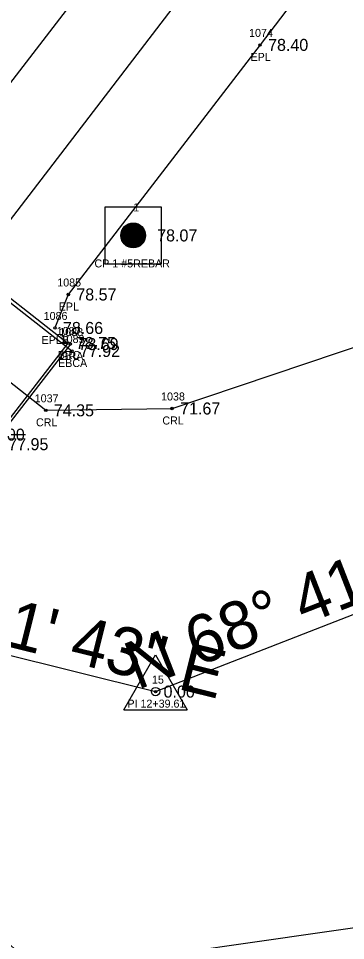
# Model space of a CAD drawing. Extents: x 2505249 to 2506333, y 912937 to 914171.
# Drawn here: x 2505829.2 to 2505870.1, y 913450.7 to 913565.9 of the extents above; entities that cross this region are included whole.
import ezdxf

# ---------------------------------------------------------------- set-up
doc = ezdxf.new("R2010")
doc.units = 0
for name, color, linetype in [('RD_EX_Bridge', 7, 'Continuous'), ('RD_EX_Bridge_txCode', 7, 'Continuous'), ('RD_EX_GuardRail', 7, 'Continuous'), ('RD_EX_GuardRail_txCode', 7, 'Continuous'), ('RD_EX_H2O', 7, 'Continuous'), ('RD_EX_H2O_txCode', 7, 'Continuous'), ('RD_EX_Misc', 7, 'Continuous'), ('RD_EX_Road', 7, 'Continuous'), ('RD_EX_Road_txCode', 7, 'Continuous'), ('RD_EX_TX_Bridge_ELEV', 7, 'Continuous'), ('RD_EX_TX_GuardRail_ELEV', 7, 'Continuous'), ('RD_EX_TX_H2O_ELEV', 7, 'Continuous'), ('RD_EX_TX_Misc_ELEV', 7, 'Continuous'), ('RD_EX_TX_Road_ELEV', 7, 'Continuous'), ('RD_HC_Cl', 7, 'Continuous'), ('RD_HC_Data', 7, 'Continuous'), ('RD_HC_Survey', 7, 'Continuous'), ('RD_HC_Survey_ELEV', 7, 'Continuous'), ('RD_HC_Survey_txCode', 7, 'Continuous'), ('RD_HC_txCode', 7, 'Continuous'), ('RD_SMD_Locator', 7, 'Continuous')]:
    doc.layers.add(name, color=color, linetype=linetype)

msp = doc.modelspace()

# ---------------------------------------------------------------- linework, layer by layer
at = {"layer": 'RD_EX_Bridge'}
msp.add_line((2505835.88, 913524.37), (2505809.62, 913544.86), dxfattribs=at)
msp.add_lwpolyline([(2505810.9, 913544.51), (2505835.38, 913525.37), (2505780.21, 913454.04), (2505755.58, 913473.5), (2505810.9, 913544.51)], dxfattribs=at)
at = {"layer": 'RD_EX_GuardRail'}
msp.add_line((2505835.7, 913525.24), (2505780.23, 913453.67), dxfattribs=at)
at = {"layer": 'RD_EX_H2O'}
for points in [[(2505762.26, 913658.11), (2505746.15, 913644.25), (2505726.47, 913615.21), (2505674.21, 913628.01), (2505666.25, 913620.58), (2505714.6, 913592.15), (2505793.9, 913560.45), (2505801.32, 913552.8), (2505803.7, 913539.77), (2505832.63, 913516.96), (2505848.42, 913517.19), (2505881.86, 913528.44), (2505910.2, 913538.78), (2505939.3, 913544.45), (2505946.25, 913542.54), (2505974.65, 913535.18), (2506004.11, 913524.7), (2506052.03, 913515.47), (2506115.49, 913494.68), (2506138.05, 913548.89)], [(2505789.47, 913464.31), (2505795.69, 913463.1), (2505812.13, 913464.37), (2505832.03, 913446.73), (2505876.17, 913453.08), (2505891.76, 913474.03), (2505941.74, 913475.13), (2505995.42, 913465.05), (2506040.13, 913447.4), (2506076.3, 913432.47), (2506096.96, 913385.48)]]:
    msp.add_lwpolyline(points, dxfattribs=at)
at = {"layer": 'RD_EX_Misc'}
msp.add_line((2505820.09, 913513.92), (2505830.09, 913513.92), dxfattribs=at)
at = {"layer": 'RD_EX_Road'}
for points in [[(2506024.03, 913813.1), (2505962.01, 913732.06), (2505903.3, 913655.93), (2505840.88, 913574.4), (2505819.41, 913546.54), (2505814.19, 913542.64)], [(2506040.71, 913800.23), (2505979.73, 913720.47), (2505920.44, 913642.61), (2505859.42, 913562.61), (2505835.44, 913531.43), (2505833.77, 913527.25)]]:
    msp.add_lwpolyline(points, dxfattribs=at)
at = {"layer": 'RD_HC_Cl'}
for p, q in [((2505792.76, 913494.51), (2506032.34, 913807.1)), ((2505846.35, 913481.82), (2505891.84, 913499.56)), ((2505811.03, 913490.61), (2505846.35, 913481.82))]:
    msp.add_line(p, q, dxfattribs=at)
at = {"layer": 'RD_HC_Data'}
for p, q in [((2505842.38, 913479.53), (2505846.35, 913486.41)), ((2505846.35, 913486.41), (2505850.32, 913479.53)), ((2505842.38, 913479.53), (2505850.32, 913479.53))]:
    msp.add_line(p, q, dxfattribs=at)
msp.add_circle((2505846.35, 913481.82), 0.529, dxfattribs=at)
at = {"layer": 'RD_HC_Survey'}
for p, q in [((2505842.24, 913537.97), (2505842.24, 913539.64)), ((2505842.29, 913537.9), (2505842.29, 913539.71)), ((2505842.34, 913537.83), (2505842.34, 913539.78)), ((2505842.39, 913537.77), (2505842.39, 913539.84)), ((2505842.44, 913537.72), (2505842.44, 913539.89)), ((2505842.49, 913537.67), (2505842.49, 913539.94)), ((2505842.54, 913537.63), (2505842.54, 913539.99)), ((2505842.59, 913537.58), (2505842.59, 913540.03)), ((2505842.64, 913537.55), (2505842.64, 913540.06)), ((2505842.69, 913537.51), (2505842.69, 913540.1)), ((2505842.74, 913537.48), (2505842.74, 913540.13)), ((2505842.79, 913537.45), (2505842.79, 913540.16)), ((2505842.84, 913537.42), (2505842.84, 913540.19)), ((2505842.89, 913537.4), (2505842.89, 913540.21)), ((2505842.94, 913537.38), (2505842.94, 913540.23)), ((2505842.99, 913537.36), (2505842.99, 913540.25)), ((2505843.04, 913537.34), (2505843.04, 913540.27)), ((2505843.09, 913537.32), (2505843.09, 913540.29)), ((2505843.14, 913537.31), (2505843.14, 913540.3)), ((2505843.19, 913537.29), (2505843.19, 913540.32)), ((2505843.24, 913537.28), (2505843.24, 913540.33)), ((2505843.29, 913537.27), (2505843.29, 913540.34)), ((2505843.34, 913537.27), (2505843.34, 913540.35)), ((2505843.39, 913537.26), (2505843.39, 913540.35)), ((2505843.44, 913537.25), (2505843.44, 913540.36)), ((2505843.49, 913537.25), (2505843.49, 913540.36)), ((2505843.54, 913537.25), (2505843.54, 913540.36)), ((2505843.59, 913537.25), (2505843.59, 913540.36)), ((2505843.64, 913537.25), (2505843.64, 913540.36)), ((2505843.69, 913537.26), (2505843.69, 913540.35)), ((2505843.74, 913537.26), (2505843.74, 913540.35)), ((2505843.79, 913537.27), (2505843.79, 913540.34)), ((2505843.84, 913537.28), (2505843.84, 913540.33)), ((2505843.89, 913537.29), (2505843.89, 913540.32)), ((2505843.94, 913537.3), (2505843.94, 913540.31)), ((2505843.99, 913537.31), (2505843.99, 913540.3)), ((2505844.04, 913537.33), (2505844.04, 913540.28)), ((2505844.09, 913537.35), (2505844.09, 913540.26)), ((2505844.14, 913537.37), (2505844.14, 913540.24)), ((2505844.19, 913537.39), (2505844.19, 913540.22)), ((2505844.24, 913537.41), (2505844.24, 913540.2)), ((2505844.29, 913537.44), (2505844.29, 913540.17)), ((2505844.34, 913537.47), (2505844.34, 913540.15)), ((2505844.39, 913537.5), (2505844.39, 913540.11)), ((2505844.44, 913537.53), (2505844.44, 913540.08)), ((2505844.49, 913537.57), (2505844.49, 913540.04)), ((2505844.54, 913537.61), (2505844.54, 913540.01)), ((2505844.59, 913537.65), (2505844.59, 913539.96)), ((2505844.64, 913537.69), (2505844.64, 913539.92)), ((2505844.69, 913537.75), (2505844.69, 913539.86)), ((2505844.74, 913537.8), (2505844.74, 913539.81)), ((2505844.79, 913537.87), (2505844.79, 913539.75)), ((2505844.84, 913537.93), (2505844.84, 913539.68)), ((2505842.04, 913538.44), (2505842.04, 913539.17)), ((2505842.09, 913538.28), (2505842.09, 913539.33)), ((2505842.14, 913538.15), (2505842.14, 913539.46)), ((2505842.19, 913538.06), (2505842.19, 913539.55)), ((2505844.89, 913538.01), (2505844.89, 913539.6)), ((2505844.94, 913538.11), (2505844.94, 913539.51)), ((2505844.99, 913538.21), (2505844.99, 913539.4)), ((2505845.04, 913538.36), (2505845.04, 913539.25)), ((2505845.09, 913538.58), (2505845.09, 913539.03))]:
    msp.add_line(p, q, dxfattribs=at)
msp.add_lwpolyline([(2505847.08, 913542.34), (2505840.01, 913542.34), (2505840.01, 913535.27), (2505847.08, 913535.27)], close=True, dxfattribs=at)
msp.add_circle((2505843.55, 913538.81), 1.55, dxfattribs=at)
at = {"layer": 'RD_SMD_Locator'}
for centre in [(2505859.42, 913562.61), (2505843.55, 913538.81), (2505835.44, 913531.43), (2505833.77, 913527.25), (2505835.38, 913525.37), (2505835.7, 913525.24), (2505835.88, 913524.37), (2505832.63, 913516.96), (2505848.42, 913517.19), (2505846.35, 913481.82)]:
    msp.add_circle(centre, 0.15, dxfattribs=at)

# ---------------------------------------------------------------- texts
at = {"layer": 'RD_EX_Bridge_txCode'}
for s, p in [('1087', (2505833.99, 913526.37)), ('1089', (2505834.49, 913525.37)), ('BRC', (2505834.12, 913523.37)), ('EBCA', (2505834.16, 913522.37))]:
    msp.add_text(s, height=1, dxfattribs=at).set_placement(p)
at = {"layer": 'RD_EX_GuardRail_txCode'}
for s, p in [('1088', (2505834.31, 913526.24)), ('GRA', (2505834.43, 913523.24))]:
    msp.add_text(s, height=1, dxfattribs=at).set_placement(p)
at = {"layer": 'RD_EX_H2O_txCode'}
for s, p in [('1037', (2505831.24, 913517.96)), ('1038', (2505847.04, 913518.19)), ('CRL', (2505831.4, 913514.96)), ('CRL', (2505847.2, 913515.19))]:
    msp.add_text(s, height=1, dxfattribs=at).set_placement(p)
at = {"layer": 'RD_EX_Road_txCode'}
for s, p in [('1074', (2505858.04, 913563.61)), ('EPL', (2505858.22, 913560.61)), ('1085', (2505834.06, 913532.43)), ('EPL', (2505834.24, 913529.43)), ('1086', (2505832.36, 913528.25)), ('EPLB', (2505832.09, 913525.25))]:
    msp.add_text(s, height=1, dxfattribs=at).set_placement(p)
at = {"layer": 'RD_EX_TX_Bridge_ELEV'}
for s, p in [('78.75', (2505836.38, 913524.62)), ('77.92', (2505836.88, 913523.62)), ('77.95', (2505827.93, 913511.98))]:
    msp.add_text(s, height=1.5, dxfattribs=at).set_placement(p)
at = {"layer": 'RD_EX_TX_GuardRail_ELEV'}
msp.add_text('78.69', height=1.5, dxfattribs=at).set_placement((2505836.7, 913524.49))
at = {"layer": 'RD_EX_TX_H2O_ELEV'}
for s, p in [('71.67', (2505849.42, 913516.44)), ('74.35', (2505833.63, 913516.21))]:
    msp.add_text(s, height=1.5, dxfattribs=at).set_placement(p)
at = {"layer": 'RD_EX_TX_Misc_ELEV'}
msp.add_text('0.00', height=1.5, dxfattribs=at).set_placement((2505826.09, 913513.17))
at = {"layer": 'RD_EX_TX_Road_ELEV'}
for s, p in [('78.40', (2505860.42, 913561.86)), ('78.57', (2505836.44, 913530.68)), ('78.66', (2505834.77, 913526.5))]:
    msp.add_text(s, height=1.5, dxfattribs=at).set_placement(p)
at = {"layer": 'RD_HC_Data'}
for s, rotation, p in [('N 68%%d 41\' 41" E', 21.3052, (2505844.06, 913482)), ('S 76%%d 01\' 43" E', 346.0287, (2505801.77, 913493.94))]:
    msp.add_text(s, height=6, rotation=rotation, dxfattribs=at).set_placement(p)
at = {"layer": 'RD_HC_Survey_ELEV'}
for s, p in [('78.07', (2505846.55, 913538.06)), ('0.00', (2505847.35, 913481.07))]:
    msp.add_text(s, height=1.5, dxfattribs=at).set_placement(p)
at = {"layer": 'RD_HC_Survey_txCode'}
for s, p in [('1', (2505843.55, 913541.81)), ('CP 1 #5REBAR', (2505838.71, 913534.81))]:
    msp.add_text(s, height=1, dxfattribs=at).set_placement(p)
at = {"layer": 'RD_HC_txCode'}
for s, p in [('15', (2505845.9, 913482.82)), ('PI 12+39.61', (2505842.83, 913479.82))]:
    msp.add_text(s, height=1, dxfattribs=at).set_placement(p)

doc.saveas('drawing.dxf')
